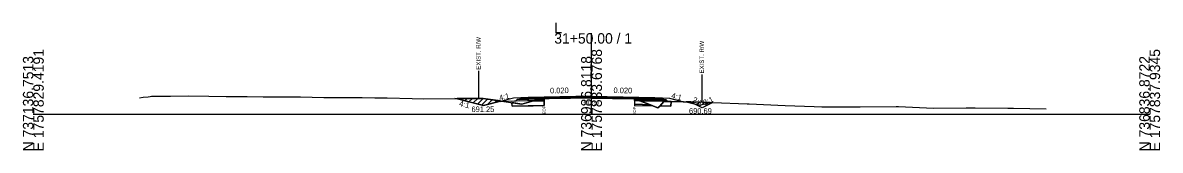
# Model space of a CAD drawing. Extents: x -26 to 4303, y -10 to 9577.
# Drawn here: x 1997.2 to 2302.8, y 1490.3 to 1524.5 of the extents above; entities that cross this region are included whole.
import ezdxf

# ---------------------------------------------------------------- set-up
doc = ezdxf.new("R2010")
doc.units = 0
for name, color, linetype in [('Default', 7, 'Continuous'), ('Exist CMT Pavement', 7, 'Continuous'), ('Old_Level_10', 7, 'Continuous'), ('Old_Level_2', 7, 'Continuous'), ('Pattern 1', 7, 'Continuous'), ('Prop CMT Conc Surface', 7, 'Continuous'), ('Prop CMT Concrete Structures', 7, 'Continuous'), ('Prop CMT Concrete Wall', 7, 'Continuous'), ('Prop CMT Pvmt Course 1', 7, 'Continuous'), ('Prop CMT Pvmt Course 1 CG', 7, 'Continuous'), ('Prop CMT Pvmt Course 2', 7, 'Continuous'), ('Prop CMT Pvmt Course 2 Wedge', 7, 'Continuous'), ('Prop CMT Pvmt Course 3', 7, 'Continuous'), ('Prop CMT Pvmt Surface', 7, 'Continuous'), ('Prop CMT Pvmt Surface Shoulder', 7, 'Continuous'), ('Prop CMT Pvmt Wedge Surface 1', 7, 'Continuous'), ('Prop CMT Pvmt Wedge Surface 2', 7, 'Continuous'), ('Prop CMT Pvmt Wedge Surface 3', 7, 'Continuous'), ('Prop CMT Shld Paved Course 1', 7, 'Continuous'), ('Prop CMT Shld Paved Course 2', 7, 'Continuous'), ('Prop CMT Shld Paved Course 3', 7, 'Continuous'), ('Prop CMT Slope Grass', 7, 'Continuous'), ('Prop CMT Subgrade Earthwork', 7, 'Continuous'), ('Prop Road Sect_ Recs - UC Shallow (Outline)', 7, 'Continuous'), ('Prop Shade Light', 7, 'Continuous'), ('Prop XS DDE Elevations', 7, 'Continuous'), ('Prop XS Ditch Standard Text', 7, 'Continuous'), ('Prop XS Earthwork Shape', 7, 'Continuous'), ('Prop XS Hydro Elevations', 7, 'Continuous'), ('Prop XS SE Text', 7, 'Continuous'), ('Prop XS Side Slope Text', 7, 'Continuous'), ('Prop XS Wedging', 7, 'Continuous'), ('Scratch_Level_9', 7, 'Continuous')]:
    doc.layers.add(name, color=color, linetype=linetype)

msp = doc.modelspace()

# ---------------------------------------------------------------- linework, layer by layer
at = {"layer": 'Exist CMT Pavement'}
for points in [[(2150, 1504.79), (2133, 1504.45)], [(2150, 1504.79), (2167, 1504.45)]]:
    msp.add_lwpolyline(points, dxfattribs=at)
at = {"layer": 'Old_Level_10'}
for p, q in [((2176.7, 1503.22), (2174.7, 1503.32)), ((2179.76, 1501.69), (2176.7, 1503.22)), ((2182.64, 1503.13), (2179.76, 1501.69))]:
    msp.add_line(p, q, dxfattribs=at)
at = {"layer": 'Old_Level_2'}
for p, q in [((2150, 1500), (2150, 1521.74)), ((2150, 1500), (2150, 1521.74)), ((2000, 1500), (2150, 1500)), ((2000, 1500), (2150, 1500)), ((2150, 1500), (2300, 1500)), ((2150, 1500), (2300, 1500))]:
    msp.add_line(p, q, dxfattribs=at)
at = {"layer": 'Pattern 1'}
for p, q in [((2114.9, 1503.94), (2115.16, 1504.2)), ((2116.03, 1503.66), (2116.58, 1504.21)), ((2117.16, 1503.37), (2118, 1504.22)), ((2118.29, 1503.09), (2119.43, 1504.23)), ((2119.43, 1502.81), (2120.85, 1504.24)), ((2120.56, 1502.53), (2122.09, 1504.06)), ((2136.44, 1503.81), (2136.99, 1504.36)), ((2161.63, 1503.85), (2161.83, 1504.05)), ((2122.15, 1502.7), (2123.32, 1503.88)), ((2124.03, 1503.17), (2124.55, 1503.7)), ((2176.09, 1503.14), (2176.24, 1503.29)), ((2177.22, 1502.86), (2177.62, 1503.26)), ((2178.35, 1502.58), (2179, 1503.23)), ((2179.81, 1502.62), (2180.37, 1503.18)), ((2181.69, 1503.09), (2181.75, 1503.14))]:
    msp.add_line(p, q, dxfattribs=at)
for points in [[(2121, 1502.42), (2125.54, 1503.55), (2120.88, 1504.24), (2113.91, 1504.19)], [(2137.26, 1503.83), (2137.26, 1504.44), (2135.01, 1503.78)], [(2179, 1502.42), (2181.9, 1503.14), (2181.05, 1503.16), (2179.62, 1503.21), (2176.72, 1503.28), (2175.45, 1503.3)]]:
    msp.add_lwpolyline(points, close=True, dxfattribs=at)
msp.add_lwpolyline([(2161.55, 1504.16), (2161.55, 1503.85), (2162.35, 1503.83), (2161.55, 1504.16)], dxfattribs=at)
at = {"layer": 'Prop CMT Conc Surface'}
for points in [[(2137.26, 1504.28), (2133, 1504.2)], [(2133, 1504.2), (2133, 1503.99)], [(2133, 1503.99), (2137.26, 1504.07)], [(2137.26, 1504.07), (2137.26, 1504.28)], [(2161.55, 1504.1), (2161.55, 1504.3)], [(2161.55, 1504.3), (2167, 1504.2)], [(2167, 1503.99), (2161.55, 1504.1)], [(2167, 1504.2), (2167, 1503.99)]]:
    msp.add_lwpolyline(points, dxfattribs=at)
at = {"layer": 'Prop CMT Concrete Structures'}
for points in [[(2133, 1504.2), (2133, 1504.45)], [(2137.26, 1504.28), (2133, 1504.2)], [(2150, 1504.66), (2137.26, 1504.41)], [(2137.26, 1504.41), (2137.26, 1504.28)], [(2150, 1504.66), (2161.55, 1504.43)], [(2161.55, 1504.43), (2161.55, 1504.3)], [(2161.55, 1504.3), (2167, 1504.2)], [(2167, 1504.2), (2167, 1504.45)]]:
    msp.add_lwpolyline(points, dxfattribs=at)
at = {"layer": 'Prop CMT Pvmt Course 1'}
for points in [[(2137.26, 1504.07), (2133, 1503.99)], [(2133, 1503.99), (2133, 1503.65)], [(2137.26, 1503.74), (2137.26, 1504.07)], [(2161.55, 1504.1), (2167, 1503.99)], [(2161.55, 1503.76), (2161.55, 1504.1)], [(2167, 1503.99), (2167, 1503.65)], [(2133, 1503.65), (2137.26, 1503.74)], [(2167, 1503.65), (2161.55, 1503.76)]]:
    msp.add_lwpolyline(points, dxfattribs=at)
at = {"layer": 'Prop CMT Pvmt Course 2'}
for points in [[(2133, 1504.45), (2131, 1504.41), (2130.74, 1504.15)], [(2130.74, 1504.15), (2133, 1504.2)], [(2133, 1504.2), (2133, 1504.45)], [(2167, 1504.45), (2169, 1504.41), (2169.26, 1504.15)], [(2167, 1504.2), (2167, 1504.45)], [(2169.26, 1504.15), (2167, 1504.2)]]:
    msp.add_lwpolyline(points, dxfattribs=at)
at = {"layer": 'Prop CMT Pvmt Course 2 Wedge'}
for points in [[(2131, 1504.41), (2129, 1504.25), (2121, 1502.25), (2113.26, 1504.18)], [(2169, 1504.41), (2171, 1504.25), (2174.7, 1503.32)], [(2182.54, 1503.13), (2182.54, 1503.13)]]:
    msp.add_lwpolyline(points, dxfattribs=at)
at = {"layer": 'Prop CMT Pvmt Course 3'}
for points in [[(2133, 1504.2), (2130.74, 1504.15), (2130.53, 1503.94)], [(2130.53, 1503.94), (2133, 1503.99)], [(2133, 1503.99), (2133, 1504.2)], [(2167, 1504.2), (2169.26, 1504.15), (2169.47, 1503.94)], [(2167, 1503.99), (2167, 1504.2)], [(2169.47, 1503.94), (2167, 1503.99)]]:
    msp.add_lwpolyline(points, dxfattribs=at)
at = {"layer": 'Prop CMT Pvmt Surface'}
for points in [[(2150, 1504.54), (2133, 1504.2)], [(2133, 1504.2), (2133, 1504.45)], [(2150, 1504.54), (2167, 1504.2)], [(2167, 1504.2), (2167, 1504.45)]]:
    msp.add_lwpolyline(points, dxfattribs=at)
at = {"layer": 'Prop CMT Pvmt Surface Shoulder'}
for points in [[(2137.26, 1504.44), (2137.56, 1504.53), (2137.79, 1504.54), (2138.03, 1504.54), (2138.1, 1504.54), (2138.56, 1504.54), (2138.93, 1504.54), (2140.56, 1504.54), (2140.89, 1504.54), (2143.06, 1504.56), (2143.32, 1504.57), (2145.56, 1504.56), (2145.75, 1504.56), (2148.06, 1504.56), (2148.12, 1504.56), (2148.76, 1504.56), (2149.02, 1504.56), (2149.17, 1504.56), (2149.58, 1504.56), (2150, 1504.56)], [(2150, 1504.56), (2150.02, 1504.56), (2150.18, 1504.56), (2150.55, 1504.56), (2150.56, 1504.56), (2150.62, 1504.56), (2152.58, 1504.51), (2153.05, 1504.5), (2153.06, 1504.5), (2155.48, 1504.44), (2155.56, 1504.44), (2157.91, 1504.34), (2158.06, 1504.34), (2158.43, 1504.33), (2160.65, 1504.25), (2160.83, 1504.26), (2161.04, 1504.26), (2161.08, 1504.26), (2161.09, 1504.26), (2161.09, 1504.26), (2161.13, 1504.26), (2161.23, 1504.25), (2161.35, 1504.24), (2161.55, 1504.16)]]:
    msp.add_lwpolyline(points, dxfattribs=at)
at = {"layer": 'Prop CMT Pvmt Wedge Surface 1'}
for p, q in [((2133.02, 1503.53), (2125.53, 1503.38)), ((2137.26, 1503.61), (2133.02, 1503.53)), ((2161.55, 1503.64), (2166.98, 1503.53)), ((2166.98, 1503.53), (2174.47, 1503.38))]:
    msp.add_line(p, q, dxfattribs=at)
for points in [[(2137.26, 1503.61), (2137.26, 1504.44)], [(2161.55, 1503.64), (2161.55, 1504.16)]]:
    msp.add_lwpolyline(points, dxfattribs=at)
at = {"layer": 'Prop CMT Pvmt Wedge Surface 2'}
for points in [[(2150, 1504.56), (2149.58, 1504.56), (2149.17, 1504.56), (2149.02, 1504.56), (2148.76, 1504.56), (2148.12, 1504.56), (2148.06, 1504.56), (2145.75, 1504.56), (2145.56, 1504.56), (2145.22, 1504.57)], [(2145.22, 1504.57), (2145.56, 1504.57)], [(2145.56, 1504.57), (2145.75, 1504.58), (2148.06, 1504.62), (2148.12, 1504.62), (2148.76, 1504.64), (2149.02, 1504.64), (2149.17, 1504.64), (2149.58, 1504.65), (2150, 1504.66)], [(2150, 1504.66), (2150, 1504.56)], [(2150, 1504.66), (2150.02, 1504.66), (2150.18, 1504.66), (2150.55, 1504.65), (2150.56, 1504.65), (2150.62, 1504.65), (2152.58, 1504.61), (2153.05, 1504.6), (2153.06, 1504.6), (2155.48, 1504.55), (2155.56, 1504.55), (2157.91, 1504.5), (2158.06, 1504.5), (2158.43, 1504.49), (2160.65, 1504.45), (2160.83, 1504.44), (2161.04, 1504.44), (2161.08, 1504.44), (2161.09, 1504.44), (2161.09, 1504.44), (2161.13, 1504.44), (2161.23, 1504.44), (2161.35, 1504.43), (2161.55, 1504.43)], [(2161.55, 1504.3), (2161.35, 1504.31), (2161.23, 1504.31), (2161.13, 1504.31), (2161.09, 1504.31), (2161.09, 1504.31), (2161.08, 1504.31), (2161.04, 1504.31), (2160.83, 1504.32), (2160.65, 1504.32), (2158.43, 1504.37), (2158.06, 1504.37), (2157.91, 1504.38), (2156.24, 1504.41), (2155.56, 1504.44), (2155.48, 1504.44), (2153.06, 1504.5), (2153.05, 1504.5), (2152.58, 1504.51), (2150.62, 1504.56), (2150.56, 1504.56), (2150.55, 1504.56), (2150.18, 1504.56), (2150.02, 1504.56), (2150, 1504.56)], [(2161.55, 1504.43), (2161.55, 1504.3)]]:
    msp.add_lwpolyline(points, dxfattribs=at)
at = {"layer": 'Prop CMT Pvmt Wedge Surface 3'}
for points in [[(2161.55, 1504.16), (2161.35, 1504.24), (2161.23, 1504.25), (2161.13, 1504.26), (2161.09, 1504.26), (2161.09, 1504.26), (2161.08, 1504.26), (2161.04, 1504.26), (2160.83, 1504.26), (2160.65, 1504.25), (2158.43, 1504.33), (2158.06, 1504.34), (2157.91, 1504.34), (2156.24, 1504.41)], [(2156.24, 1504.41), (2157.91, 1504.38)], [(2157.91, 1504.38), (2158.06, 1504.37), (2158.43, 1504.37), (2160.65, 1504.32), (2160.83, 1504.32), (2161.04, 1504.31), (2161.08, 1504.31), (2161.09, 1504.31), (2161.09, 1504.31), (2161.13, 1504.31), (2161.23, 1504.31), (2161.35, 1504.31), (2161.55, 1504.3)], [(2161.55, 1504.3), (2161.55, 1504.16)]]:
    msp.add_lwpolyline(points, dxfattribs=at)
at = {"layer": 'Prop CMT Shld Paved Course 1'}
for points in [[(2133, 1503.99), (2133, 1504.45)], [(2150, 1504.33), (2133, 1503.99)], [(2150, 1504.33), (2167, 1503.99)], [(2167, 1503.99), (2167, 1504.45)]]:
    msp.add_lwpolyline(points, dxfattribs=at)
at = {"layer": 'Prop CMT Shld Paved Course 2'}
for points in [[(2133, 1504.45), (2131, 1504.41)], [(2167, 1504.45), (2169, 1504.41)]]:
    msp.add_lwpolyline(points, dxfattribs=at)
at = {"layer": 'Prop CMT Shld Paved Course 3'}
for points in [[(2150, 1504.79), (2133, 1504.45)], [(2133, 1504.45), (2133, 1504.2)], [(2133, 1504.2), (2137.26, 1504.28)], [(2137.26, 1504.41), (2150, 1504.66)], [(2137.26, 1504.28), (2137.26, 1504.41)], [(2150, 1504.54), (2150, 1504.79)], [(2150, 1504.79), (2167, 1504.45)], [(2150, 1504.66), (2150, 1504.54), (2150, 1504.54)], [(2161.55, 1504.43), (2150, 1504.66)], [(2161.55, 1504.3), (2161.55, 1504.43)], [(2167, 1504.2), (2161.55, 1504.3)], [(2167, 1504.45), (2167, 1504.2)]]:
    msp.add_lwpolyline(points, dxfattribs=at)
at = {"layer": 'Prop CMT Slope Grass'}
msp.add_lwpolyline([(2028.5, 1504.4), (2029.52, 1504.54), (2030.9, 1504.66), (2031.4, 1504.73), (2031.77, 1504.86), (2036.86, 1504.86), (2041.77, 1504.89), (2047.16, 1504.85), (2051.78, 1504.78), (2057.46, 1504.71), (2061.78, 1504.66), (2067.76, 1504.68), (2071.79, 1504.64), (2078.05, 1504.43), (2081.79, 1504.48), (2088.35, 1504.45), (2091.8, 1504.37), (2095.06, 1504.34), (2101.8, 1504.2), (2104.79, 1504.12), (2118.52, 1504.22), (2120.88, 1504.24), (2126.41, 1503.42), (2131.27, 1502.69), (2136.58, 1504.24), (2137.56, 1504.53), (2138.1, 1504.54), (2138.56, 1504.54), (2138.93, 1504.54), (2140.56, 1504.54), (2143.32, 1504.57), (2145.75, 1504.56), (2148.12, 1504.56), (2149.17, 1504.56), (2149.58, 1504.56), (2150.18, 1504.56), (2150.62, 1504.56), (2152.58, 1504.51), (2153.06, 1504.5), (2155.56, 1504.44), (2158.06, 1504.34), (2158.43, 1504.33), (2161.08, 1504.26), (2161.35, 1504.24), (2162.13, 1503.92), (2167.81, 1501.73), (2168.37, 1502.14), (2169.44, 1503.43), (2179.82, 1503.21), (2181.19, 1503.15), (2182.62, 1503.13), (2191.85, 1502.8), (2192.35, 1502.75), (2202.08, 1502.32), (2209.81, 1502.05), (2211.92, 1501.98), (2221.87, 1501.98), (2222.22, 1501.97), (2231.87, 1502.05), (2232.52, 1502.05), (2241.88, 1501.62), (2250.72, 1501.66), (2251.88, 1501.65), (2253.11, 1501.65), (2261.89, 1501.62), (2263.41, 1501.62), (2272.14, 1501.46)], dxfattribs=at)
at = {"layer": 'Prop CMT Subgrade Earthwork'}
for points in [[(2133, 1503.99), (2130.53, 1503.94), (2130.03, 1503.93), (2129.69, 1503.59)], [(2133, 1503.65), (2133, 1503.99)], [(2167, 1503.99), (2169.47, 1503.94), (2169.97, 1503.93), (2170.31, 1503.59)], [(2167, 1503.65), (2167, 1503.99)], [(2129.69, 1503.59), (2133, 1503.65)], [(2170.31, 1503.59), (2167, 1503.65)]]:
    msp.add_lwpolyline(points, dxfattribs=at)
at = {"layer": 'Prop Road Sect_ Recs - UC Shallow (Outline)'}
for points in [[(2128.64, 1502.15), (2128.62, 1503.09), (2131.27, 1502.69), (2135.01, 1503.78), (2137.26, 1503.83), (2137.26, 1502.33)], [(2161.55, 1503.85), (2161.55, 1502.35), (2166.45, 1502.26), (2162.35, 1503.83)], [(2168.42, 1502.21), (2168.48, 1502.28), (2169.44, 1503.43), (2171.39, 1503.39), (2171.36, 1502.15)]]:
    msp.add_lwpolyline(points, close=True, dxfattribs=at)
at = {"layer": 'Prop Shade Light'}
for p, q in [((2128.63, 1502.67), (2128.64, 1502.15)), ((2128.64, 1502.15), (2130.45, 1502.19)), ((2130.45, 1502.19), (2131.53, 1502.21)), ((2131.53, 1502.21), (2134.28, 1502.27)), ((2137.26, 1503.51), (2134.41, 1503.61)), ((2162.35, 1503.83), (2161.55, 1503.85)), ((2161.55, 1503.85), (2161.55, 1502.65)), ((2161.55, 1502.65), (2165.82, 1502.5)), ((2165.82, 1502.5), (2161.55, 1502.65)), ((2161.55, 1502.65), (2161.55, 1502.35)), ((2161.55, 1502.35), (2166.45, 1502.26)), ((2165.82, 1502.5), (2162.35, 1503.83)), ((2166.45, 1502.26), (2165.82, 1502.5)), ((2169.44, 1503.43), (2168.42, 1502.21)), ((2168.42, 1502.21), (2171.36, 1502.15)), ((2171.39, 1503.39), (2169.44, 1503.43)), ((2171.36, 1502.15), (2171.39, 1503.39))]:
    msp.add_line(p, q, dxfattribs=at)
for points in [[(2134.41, 1503.61), (2131.27, 1502.69), (2128.62, 1503.09), (2128.63, 1502.67)], [(2134.28, 1502.27), (2137.26, 1502.33), (2137.26, 1503.51)]]:
    msp.add_lwpolyline(points, dxfattribs=at)
at = {"layer": 'Prop XS DDE Elevations'}
for points in [[(2125.53, 1503.38), (2121, 1502.25), (2113.26, 1504.18), (2118.52, 1504.22), (2120.88, 1504.24), (2125.97, 1503.49)], [(2134.23, 1503.55), (2136.58, 1504.24), (2137.26, 1504.44), (2137.26, 1503.61)], [(2137.56, 1504.53), (2138.1, 1504.54), (2138.03, 1504.54), (2137.79, 1504.54)], [(2140.89, 1504.54), (2142.12, 1504.55), (2140.56, 1504.54)], [(2142.12, 1504.55), (2143.06, 1504.56), (2143.32, 1504.57)], [(2143.32, 1504.57), (2145.56, 1504.56), (2145.75, 1504.56)], [(2148.76, 1504.56), (2149.17, 1504.56), (2149.02, 1504.56)], [(2149.58, 1504.56), (2150.18, 1504.56), (2150.02, 1504.56), (2150, 1504.56)], [(2150.55, 1504.56), (2150.56, 1504.56), (2150.62, 1504.56), (2150.18, 1504.56)], [(2155.56, 1504.44), (2158.06, 1504.34), (2157.91, 1504.34)], [(2161.04, 1504.26), (2161.08, 1504.26), (2158.43, 1504.33), (2160.65, 1504.25), (2160.83, 1504.26)], [(2161.13, 1504.26), (2161.23, 1504.25), (2161.35, 1504.24), (2161.08, 1504.26)], [(2161.55, 1503.64), (2162.93, 1503.61), (2162.13, 1503.92), (2161.55, 1504.16)], [(2126.41, 1503.42), (2126.56, 1503.4), (2125.53, 1503.38), (2125.97, 1503.49)], [(2126.56, 1503.4), (2131.27, 1502.69), (2134.23, 1503.55), (2133.02, 1503.53)], [(2174.47, 1503.38), (2174.7, 1503.32), (2169.44, 1503.43), (2168.37, 1502.14), (2167.81, 1501.73), (2162.93, 1503.61), (2166.98, 1503.53)]]:
    msp.add_lwpolyline(points, close=True, dxfattribs=at)
at = {"layer": 'Prop XS Ditch Standard Text'}
for p, q in [((2119.62, 1511.63), (2119.62, 1504.23)), ((2179.62, 1510.61), (2179.62, 1503.21)), ((2137.26, 1504.44), (2137.26, 1502.39)), ((2161.55, 1504.16), (2161.55, 1502.11))]:
    msp.add_line(p, q, dxfattribs=at)
at = {"layer": 'Prop XS Earthwork Shape'}
msp.add_lwpolyline([(2182.6, 1503.13), (2179.74, 1501.7), (2176.7, 1503.22), (2174.7, 1503.32), (2179.82, 1503.21), (2181.19, 1503.15)], close=True, dxfattribs=at)
at = {"layer": 'Prop XS Wedging'}
for q in [(2161.55, 1504.69), (2161.55, 1504.43)]:
    msp.add_line((2161.55, 1504.16), q, dxfattribs=at)
for points in [[(2150, 1504.66), (2133, 1504.32)], [(2150, 1504.66), (2150, 1504.66), (2145.19, 1504.56)], [(2145.19, 1504.56), (2145.75, 1504.56), (2148.12, 1504.56), (2149.17, 1504.56), (2149.58, 1504.56), (2150.18, 1504.56), (2150.62, 1504.56), (2152.58, 1504.51), (2153.06, 1504.5), (2155.56, 1504.44), (2158.06, 1504.34), (2158.43, 1504.33), (2161.08, 1504.26), (2161.35, 1504.24), (2161.55, 1504.16)], [(2150, 1504.66), (2167, 1504.32)], [(2161.55, 1504.43), (2150, 1504.66), (2150, 1504.66)], [(2161.55, 1504.16), (2161.55, 1504.16)]]:
    msp.add_lwpolyline(points, dxfattribs=at)
at = {"layer": 'Scratch_Level_9'}
for p, q in [((2134.69, 1503.69), (2134.41, 1503.61)), ((2134.41, 1503.61), (2137.26, 1503.51)), ((2135.01, 1503.78), (2134.69, 1503.69)), ((2136.44, 1503.81), (2135.01, 1503.78)), ((2137.26, 1503.83), (2136.44, 1503.81)), ((2137.26, 1503.51), (2137.26, 1503.83))]:
    msp.add_line(p, q, dxfattribs=at)

# ---------------------------------------------------------------- texts
at = {"layer": 'Default'}
msp.add_text('-', height=0.0001, dxfattribs=at).set_placement((2000, 1500))
at = {"layer": 'Old_Level_2'}
for s, p in [('L', (2140, 1521.74)), ('L', (2140, 1521.74)), ('31+50.00 / 1', (2140, 1518.94)), ('31+50.00 / 1', (2140, 1518.94))]:
    msp.add_text(s, height=2.8, dxfattribs=at).set_placement(p)
for s, p in [('E 1757829.4191', (2002.8, 1490)), ('E 1757829.4191', (2002.8, 1490)), ('E 1757833.6768', (2152.8, 1490)), ('E 1757833.6768', (2152.8, 1490)), ('E 1757837.9345', (2302.8, 1490)), ('E 1757837.9345', (2302.8, 1490)), ('N 737136.7513', (2000, 1490)), ('N 737136.7513', (2000, 1490)), ('N 736986.8118', (2150, 1490)), ('N 736986.8118', (2150, 1490)), ('N 736836.8722', (2300, 1490)), ('N 736836.8722', (2300, 1490))]:
    msp.add_text(s, height=2.8, rotation=90, dxfattribs=at).set_placement(p)
at = {"layer": 'Prop CMT Concrete Wall'}
for rotation, p in [(334.1383, (2176.98, 1503.35)), (25.8617, (2180.42, 1502.27))]:
    msp.add_text('2:1', height=1.5, rotation=rotation, dxfattribs=at).set_placement(p)
msp.add_text('690.69', height=1.5, dxfattribs=at).set_placement((2176.2, 1500.11))
at = {"layer": 'Prop CMT Pvmt Course 1 CG'}
msp.add_text('693.56', height=1, dxfattribs=at).set_placement((2147.86, 1502.56))
at = {"layer": 'Prop XS Ditch Standard Text'}
for s, height, p in [('EXIST. R/W', 1.181, (2120.21, 1511.93)), ('EXIST. R/W', 1.181, (2180.21, 1510.92)), ('EOP', 0.787, (2137.65, 1499.99)), ('EOP', 0.787, (2161.94, 1499.71))]:
    msp.add_text(s, height=height, rotation=90, dxfattribs=at).set_placement(p)
at = {"layer": 'Prop XS Hydro Elevations'}
msp.add_text('691.25', height=1.5, dxfattribs=at).set_placement((2117.75, 1500.56))
at = {"layer": 'Prop XS SE Text'}
for rotation, p in [(1.1458, (2138.86, 1505.56)), (358.8542, (2155.9, 1505.67))]:
    msp.add_text('0.020', height=1.5, rotation=rotation, dxfattribs=at).set_placement(p)
at = {"layer": 'Prop XS Side Slope Text'}
for rotation, p in [(14.0362, (2125.37, 1503.58)), (345.9638, (2171.35, 1504.32)), (345.9638, (2114.33, 1502.22))]:
    msp.add_text('4:1', height=1.5, rotation=rotation, dxfattribs=at).set_placement(p)

doc.saveas('drawing.dxf')
